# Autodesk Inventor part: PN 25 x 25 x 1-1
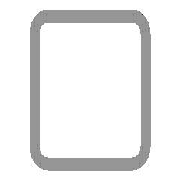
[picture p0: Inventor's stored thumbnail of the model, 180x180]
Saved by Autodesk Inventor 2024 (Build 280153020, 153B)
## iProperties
Company: ATC
Created: 2023-03
Part Number: PN 25 x 25 x 1-1
Material: Stal, miękka
Description: Rury stalowe do zastosowań precyzyjnych -  (Część 5: Rury kwadratowe, spawane, wymiarowane na zimno)
Document SubType Name: Modeling
Standard: PN
Designer: Andrzej Jaskulski
Standards Organization: PN
Language: pl-PL
Size Designation: 25 x 25 x 1
Categories: <MemberInstance><Categories><Category DisplayName="Kształtowniki konstrukcyjne" InternalName="089c4875-fa83-4c05-b084-43b9cc11f5ed" Mnemonic="GRDR"><CategoryPar
Density: 7.85 g/cm^3
Appearance: Częściowo polerowany
Checked By: A.J.
Engr Approved By: Andrzej Jaskulski
Mfg Approved By: Andrzej Jaskulski
Authority: A.J.
Stock Number: 25 x 25 x 1
_CCFamilyMember: 9
_CCFamilyDisplayName: PN EN 10305-5 (Rury kwadratowe, spawane, wymiarowane na zimno) - Rury stalowe do zastosowań precyzyjnych -  (Część 5: Rury kwadratowe, spawane, wymiarowane na z
_FrameMemberDoc: Frame Member File
_Version: 25.0.0
_GetPNFromCC: 0
IsCustomPart: 1
G_L: 704,101 mm
G_W: 25,000 mm
G_H: 25,000 mm
+D691D4FC-71BF-407E-BA48-AD1B38B8DECB+CUTDETAIL1: Połączenie narożnikowe 24,70 deg
+4D2D2CB4-5467-4B56-8263-7C69A3E0AAF8+CUTDETAIL2: Połączenie narożnikowe 24,91 deg
Author: Andrzej Jaskulski
Revision Number: 1/24
Title: A.J.: Kurs R2024-MEP
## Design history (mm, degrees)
node "Płaszczyzna początkowa"
node "Płaszczyzna końcowa"
sketch "Szkic"
  geometry: L1 (-12.5, -11)-(-12.5, 11); L2 (-11, 12.5)-(11, 12.5); L3 (12.5, 11)-(12.5, -11); L4 (11, -12.5)-(-11, -12.5); L5 (-11, 11.5)-(11, 11.5); L6 (11.5, 11)-(11.5, -11); L7 (11, -11.5)-(-11, -11.5); L8 (-11.5, -11)-(-11.5, 11); L9 (0, 18.044)-(0, -18.044) reference; L10 (-18.044, 0)-(18.044, 0) reference; A1 r 1.5 centre (-11, -11) between (-12.5, -11) and (-11, -12.5); A2 r 1.5 centre (-11, 11) between (-11, 12.5) and (-12.5, 11); A3 r 1.5 centre (11, 11) between (12.5, 11) and (11, 12.5); A4 r 1.5 centre (11, -11) between (11, -12.5) and (12.5, -11); A5 r 0.5 centre (-11, 11) between (-11, 11.5) and (-11.5, 11); A6 r 0.5 centre (11, 11) between (11.5, 11) and (11, 11.5); A7 r 0.5 centre (11, -11) between (11, -11.5) and (11.5, -11); A8 r 0.5 centre (-11, -11) between (-11.5, -11) and (-11, -11.5)
  constraints: 16 end point, 16 point on circle, 8 centre point, 8 tangent, 4 parallel, 3 equal radius, 2 perpendicular, 7 other
  dimensions: "d7" = 1.5 radius of A1 (= G_IR); "d10" = 25 distance between parallel lines of L2 L4 (= G_H); "d11" = 25 distance between parallel lines of L1 L3 (= G_W); "d12" = 1 distance between parallel lines of L3 L6 (= G_T); "d15" = 12.5 distance between parallel lines of L2 L10 (= 0.5 x d10); "d16" = 12.5 distance between parallel lines of L9 L3 (= 0.5 x d11)
extrude "Bryła" new body sketch "Szkic" stored distance "d3" = 704.1008 (= G_L); taper "d4" = 0 deg
node "Driven Length"
  sketch "Sketch3"
    geometry: L1 (0, 0)-(10, 0) reference
    constraints: 2 end point, 1 horizontal
  workplane "Work Plane3"
node "Płaszczyzna konstrukcyjna4"
feature "Podział1"
node "Płaszczyzna konstrukcyjna5"
feature "Podział2"
body "Solid1"
sketch "Sketch4"
  geometry: L1 (-2, -27.175)-(12, -27.175) reference; L2 (-2, 676.926)-(12, 676.926) reference
  dimensions: "d18" = 704.1008 distance between parallel lines of L1 L2 (derived)
other parameters: "G_W" = 25 [user parameter; used in 1 equation term], "G_H" = 25 [user parameter; used in 1 equation term], "G_T" = 1 [user parameter; used in 1 equation term], "G_IR" = 1.5 [user parameter; used in 1 equation term], "G_L" = 704.1008 (= d18) [user parameter; used in 1 equation term], "G_OFFSET_START" = 27.17503 [user parameter; used in 1 equation term], "G_OFFSET_END" = 26.92139 [user parameter; used in 1 equation term], "d13" = -27.17503 (= -G_OFFSET_START), "d14" = 676.92577 (= G_OFFSET_END + B_L), "B_L" = 650.00438 [user parameter; used in 1 equation term], "d17" = 90 deg
